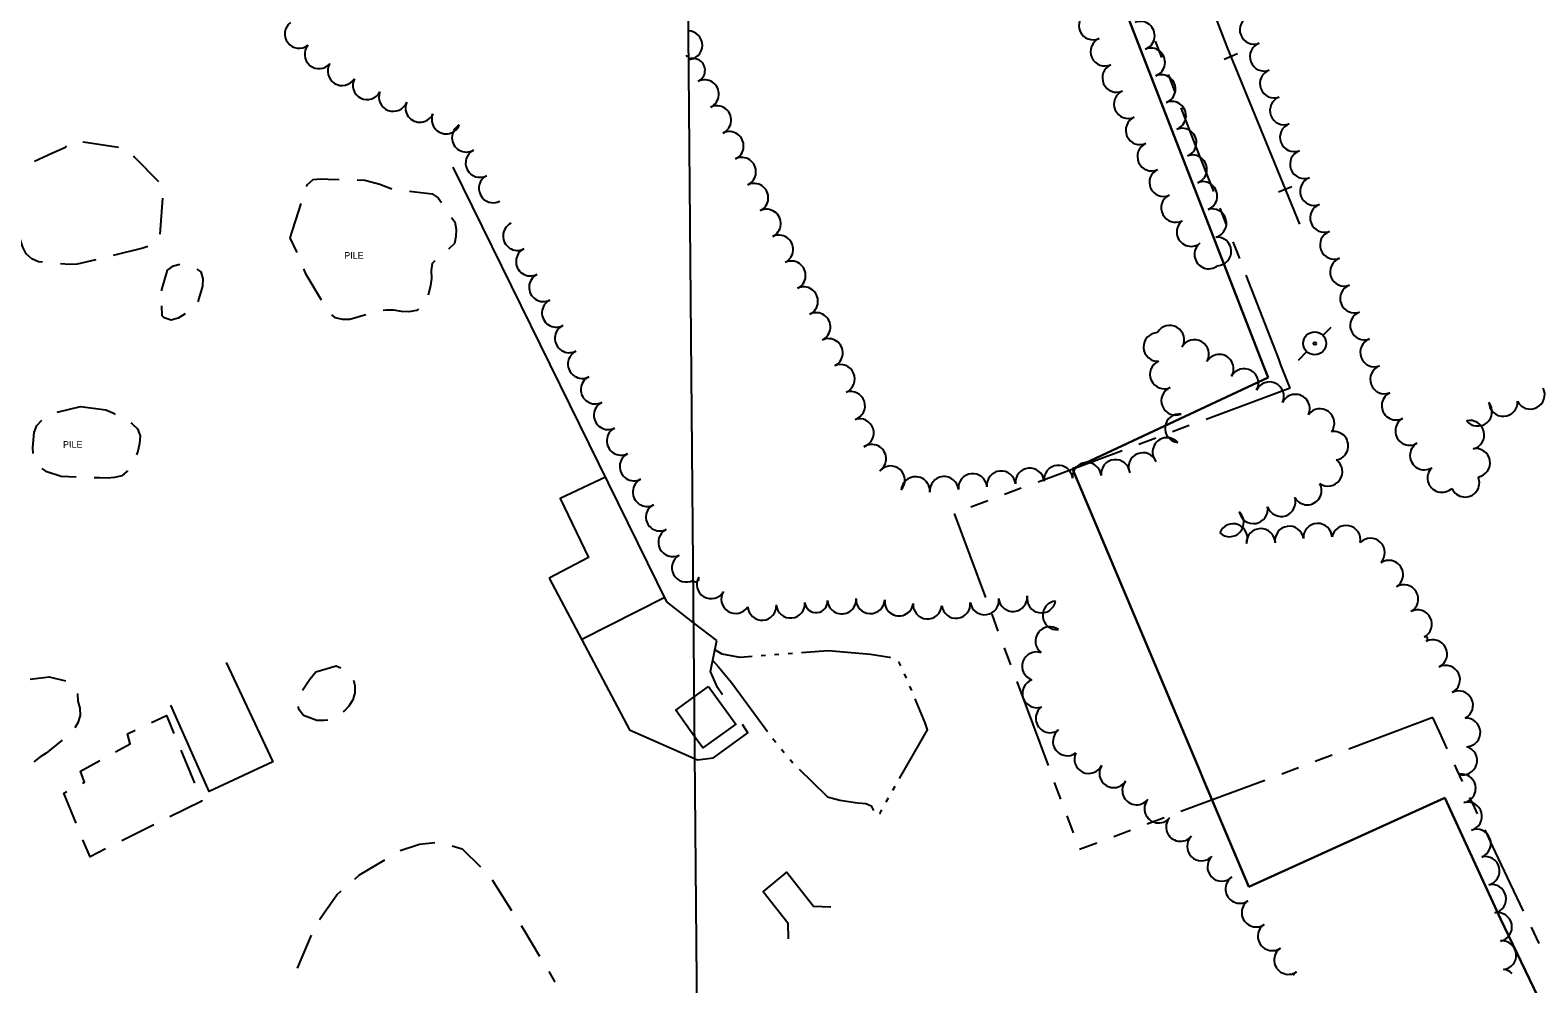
# Model space of a CAD drawing. Extents: x -2233 to 187241, y 4582 to 150524.
# Drawn here: x 104550 to 105601, y 57300 to 57965 of the extents above; entities that cross this region are included whole.
import ezdxf

# ---------------------------------------------------------------- set-up
doc = ezdxf.new("R2010")
doc.units = 0
for name, color, linetype in [('BLDG', 7, 'Continuous'), ('DIVISIONS', 7, 'Continuous'), ('DRIVWY', 7, 'Continuous'), ('DV_X_Corp_Line', 7, 'Continuous'), ('GRID', 7, 'Continuous'), ('ROAD', 7, 'Continuous'), ('RR', 7, 'Continuous'), ('TI_BORDER', 7, 'Continuous'), ('TRANSPWRLN', 7, 'Continuous'), ('TREES', 7, 'Continuous'), ('WALL', 7, 'Continuous'), ('WATER', 7, 'Continuous')]:
    doc.layers.add(name, color=color, linetype=linetype)

msp = doc.modelspace()

# ---------------------------------------------------------------- linework, layer by layer
at = {"layer": 'BLDG'}
for p, q in [((104642.7, 57847.4), (104640.8, 57822.5)), ((104731.6, 57819.9), (104739.3, 57843.7)), ((104736.5, 57809.7), (104731.6, 57819.9)), ((104569.3, 57698.4), (104585.5, 57702.3)), ((104740.3, 57504.6), (104745.3, 57512.3)), ((105013.1, 57499.9), (105023.2, 57507.2)), ((104655.4, 57462.9), (104665, 57439.8)), ((104669.8, 57428.3), (104670.1, 57427.4)), ((104670.1, 57427.4), (104647.8, 57416.3)), ((104636.6, 57410.7), (104614.2, 57399.6)), ((104872.5, 57372.4), (104885.9, 57351.2))]:
    msp.add_line(p, q, dxfattribs=at)
for points in [[(104553.4, 57873.2), (104565.6, 57878.9), (104575, 57883), (104575.9, 57883.8)], [(104587.2, 57886.8), (104589, 57886.5), (104611.9, 57883.1)], [(104622.4, 57876.9), (104623.2, 57876.1), (104639.9, 57859.1)], [(104743.1, 57855.6), (104743.6, 57857), (104747.6, 57860.4), (104752.8, 57861), (104758.1, 57860.8), (104765.8, 57860.6)], [(104778.3, 57860.2), (104783.7, 57860), (104794, 57857.2), (104802.4, 57854.1)], [(104814.7, 57852.4), (104830.5, 57850.5), (104834.7, 57847.7), (104837, 57844.4)], [(104844.1, 57834.1), (104846.4, 57830.9), (104847.4, 57825.9), (104847.1, 57820.7), (104846.2, 57815.8), (104842.5, 57812.3), (104842, 57811.9)], [(104559.1, 57802.9), (104556.2, 57803.2), (104551.5, 57805.1), (104547.5, 57808.7), (104545.3, 57813.3), (104543.7, 57818.2), (104542.9, 57819.2)], [(104632.5, 57813.8), (104629, 57812.7), (104608.3, 57807.6)], [(104596.2, 57804.6), (104583.2, 57801.4), (104577.9, 57801.2), (104571.6, 57801.8)], [(104641.9, 57782.8), (104646.1, 57797.4), (104650.2, 57800.4), (104654.8, 57801.6)], [(104666.6, 57797.9), (104669.4, 57796.2), (104670.8, 57791.3), (104670.6, 57786.1), (104667.2, 57775.2)], [(104753.5, 57776.4), (104742.8, 57794.2), (104741.2, 57798.2)], [(104832.5, 57803.8), (104830.5, 57802), (104829.9, 57797), (104830.2, 57791.6), (104829.5, 57786.6), (104827.7, 57780)], [(104658.5, 57766.9), (104653.5, 57763.8), (104648.6, 57762.4), (104643.8, 57764), (104642.4, 57765.5), (104642.2, 57772.4)], [(104784.3, 57766.1), (104773.3, 57762.9), (104768.1, 57762.9), (104763.3, 57764.2), (104760.7, 57766.3)], [(104821, 57770.1), (104819.6, 57769.2), (104814.3, 57768.2), (104809.1, 57768.4), (104803.9, 57769.4), (104798.6, 57769.4), (104796.4, 57769.1)], [(104585.5, 57702.3), (104603.2, 57699.9), (104607.9, 57697.9), (104609.6, 57696.8)], [(104552.6, 57669.5), (104552.3, 57673.7), (104553.2, 57684.3), (104555.1, 57689.1), (104558.6, 57692.7)], [(104620.6, 57690.9), (104621.6, 57690.3), (104625.2, 57686.7), (104627.1, 57681.8), (104626.6, 57676.6), (104625.4, 57671.2), (104624.4, 57668.6)], [(104582.4, 57653.1), (104572, 57653.5), (104561.9, 57656.7), (104558.7, 57659)], [(104618.2, 57657.8), (104618, 57657.3), (104614.2, 57654), (104609.2, 57652.9), (104604.2, 57652.4), (104598.8, 57652.5), (104594.9, 57652.7)], [(104550.5, 57512.2), (104563.6, 57514), (104575, 57511.1)], [(104745.3, 57512.3), (104749.5, 57517.4), (104763.6, 57521.6), (104767, 57520.2)], [(104583.2, 57502.4), (104583.3, 57502.1), (104583.7, 57497), (104585, 57492.1), (104585.2, 57487), (104583.6, 57481.9), (104581.6, 57478.4)], [(104775.7, 57511.7), (104776.7, 57507.8), (104776.8, 57502.8), (104775.3, 57497.9), (104772.5, 57493.5), (104769, 57489.8), (104768.6, 57489.5)], [(105023.2, 57507.2), (105042.2, 57481), (105019.3, 57464.5), (105013.3, 57472.7)], [(104757.8, 57483.7), (104755.4, 57483.4), (104750.3, 57483.5), (104740.9, 57486.9), (104737.9, 57490.9), (104737.3, 57493.3)], [(105013.3, 57472.7), (105000.3, 57490.7), (105013.1, 57499.9)], [(104635, 57482.1), (104645.5, 57486.9), (104650.6, 57474.5)], [(104609.9, 57461.7), (104620.1, 57467.3), (104618.2, 57474.3), (104623.6, 57476.8)], [(104572.8, 57469.7), (104561.5, 57460.7), (104557.1, 57458), (104552.9, 57454.6)], [(104586.9, 57439.9), (104588.2, 57440.6), (104585.5, 57448.3), (104598.9, 57455.7)], [(104582.4, 57411.9), (104573.8, 57432.8), (104575.9, 57434)], [(104603, 57394), (104592.1, 57388.6), (104587.2, 57400.4)], [(104808.3, 57392.9), (104821.7, 57397.4), (104832.5, 57398.5)], [(104776.6, 57373), (104780, 57376), (104797.5, 57386.5)], [(104844.6, 57396.1), (104851.4, 57394.1), (104864.3, 57381.6)], [(104752.1, 57344.9), (104764.2, 57362.1), (104767.2, 57364.8)], [(104736.8, 57310.8), (104736.8, 57310.8), (104746.4, 57333.9)], [(104892.5, 57340.7), (104894.5, 57337.6), (104905.4, 57319.2)], [(104911.8, 57308.5), (104915.9, 57301.7), (104916.1, 57301.4)]]:
    msp.add_lwpolyline(points, dxfattribs=at)
at = {"layer": 'DIVISIONS'}
for p, q in [((105339.2, 57945.4), (105334.7, 57957)), ((105348.2, 57922.1), (105343.7, 57933.7)), ((105384.3, 57828.8), (105379.8, 57840.5)), ((105420.6, 57735.6), (105397.9, 57793.8)), ((105428.6, 57715.2), (105370, 57693.3)), ((105358.3, 57689), (105346.6, 57684.6)), ((105311.5, 57671.5), (105252.9, 57649.7)), ((105334.9, 57680.3), (105323.2, 57675.9)), ((105241.2, 57645.3), (105229.5, 57640.9)), ((105217.8, 57636.6), (105206.1, 57632.2)), ((105194.4, 57627.8), (105216.2, 57569.3)), ((105220.6, 57557.6), (105224.9, 57545.8)), ((105229.3, 57534.1), (105233.7, 57522.4)), ((105238, 57510.7), (105259.9, 57452.1)), ((105528.1, 57485.5), (105469.5, 57463.6)), ((105434.4, 57450.5), (105422.7, 57446.2)), ((105457.8, 57459.3), (105446.1, 57454.9)), ((105264.2, 57440.4), (105268.6, 57428.7)), ((105411, 57441.8), (105352.4, 57420)), ((105273, 57417), (105277.4, 57405.3)), ((105340.7, 57415.6), (105329, 57411.2)), ((105293.8, 57398.1), (105281.7, 57393.6)), ((105317.3, 57406.9), (105305.6, 57402.5)), ((105602.1, 57328.2), (105596.7, 57339.4))]:
    msp.add_line(p, q, dxfattribs=at)
for points in [[(105375.3, 57852.1), (105362.7, 57884.5), (105352.7, 57910.4)], [(105393.4, 57805.5), (105391.6, 57810), (105388.9, 57817.1)], [(105428.6, 57715.2), (105422.2, 57731.4), (105420.6, 57735.6)], [(105538.1, 57463.8), (105532.7, 57475.5), (105528.1, 57485.5)], [(105548.6, 57441.1), (105545, 57449), (105543.4, 57452.5)], [(105559.2, 57418.5), (105557.3, 57422.6), (105553.9, 57429.8)], [(105591.3, 57350.7), (105582.2, 57369.7), (105569.7, 57396.1), (105564.5, 57407.2)]]:
    msp.add_lwpolyline(points, dxfattribs=at)
at = {"layer": 'DRIVWY'}
for points in [[(105032.9, 57501.4), (105029.5, 57506.5), (105024.5, 57517.7), (105028.9, 57539.3)], [(105013.5, 57457), (105015.5, 57456.1), (105026.7, 57457.6), (105050.7, 57475), (105046.9, 57480.7)]]:
    msp.add_lwpolyline(points, dxfattribs=at)
at = {"layer": 'DV_X_Corp_Line'}
for p, q in [((105409.5, 57731.9), (105253.6, 58133.5)), ((105409.5, 57731.9), (105253.6, 58133.5)), ((105253.6, 58133.5), (105409.5, 57731.9)), ((105253.6, 58133.5), (105409.5, 57731.9)), ((105286.1, 57663.1), (105413.2, 57722.5)), ((105286.1, 57663.1), (105413.2, 57722.5)), ((105413.2, 57722.5), (105286.1, 57663.1)), ((105413.2, 57722.5), (105286.1, 57663.1)), ((105413.2, 57722.5), (105409.5, 57731.9)), ((105413.2, 57722.5), (105409.5, 57731.9)), ((105409.5, 57731.9), (105413.2, 57722.5)), ((105409.5, 57731.9), (105413.2, 57722.5)), ((105277, 57658.8), (105286.1, 57663.1)), ((105277, 57658.8), (105286.1, 57663.1)), ((105286.1, 57663.1), (105277, 57658.8)), ((105286.1, 57663.1), (105277, 57658.8)), ((105365.8, 57448), (105277, 57658.8)), ((105365.8, 57448), (105277, 57658.8)), ((105277, 57658.8), (105365.8, 57448)), ((105277, 57658.8), (105365.8, 57448)), ((105367.7, 57443.4), (105365.8, 57448)), ((105367.7, 57443.4), (105365.8, 57448)), ((105365.8, 57448), (105367.7, 57443.4)), ((105365.8, 57448), (105367.7, 57443.4)), ((105399.7, 57367.7), (105367.7, 57443.4)), ((105399.7, 57367.7), (105367.7, 57443.4)), ((105367.7, 57443.4), (105399.7, 57367.7)), ((105367.7, 57443.4), (105399.7, 57367.7)), ((105536.3, 57429.6), (105399.7, 57367.7)), ((105536.3, 57429.6), (105399.7, 57367.7)), ((105399.7, 57367.7), (105536.3, 57429.6)), ((105399.7, 57367.7), (105536.3, 57429.6)), ((105575.3, 57345.2), (105536.3, 57429.6)), ((105575.3, 57345.2), (105536.3, 57429.6)), ((105536.3, 57429.6), (105575.3, 57345.2)), ((105536.3, 57429.6), (105575.3, 57345.2)), ((105601.2, 57291.2), (105575.3, 57345.2)), ((105601.2, 57291.2), (105575.3, 57345.2)), ((105575.3, 57345.2), (105601.2, 57291.2)), ((105575.3, 57345.2), (105601.2, 57291.2))]:
    msp.add_line(p, q, dxfattribs=at)
at = {"layer": 'GRID'}
msp.add_line((104991.3, 60000), (105014.8, 57302.3), dxfattribs=at)
at = {"layer": 'ROAD'}
msp.add_lwpolyline([(104912.1, 57582.7), (104968.1, 57476.9), (105013.5, 57457)], dxfattribs=at)
at = {"layer": 'RR'}
for p, q in [((105382.6, 57944.4), (105391.8, 57948.2)), ((105420.5, 57851.9), (105429.7, 57855.7))]:
    msp.add_line(p, q, dxfattribs=at)
msp.add_lwpolyline([(105007.1, 58925.1), (105096.6, 58702), (105289.2, 58201.1), (105384.5, 57953), (105435.1, 57829.4)], dxfattribs=at)
at = {"layer": 'TI_BORDER'}
msp.add_line((104999.5, 59062.3), (105026.2, 56000.1), dxfattribs=at)
at = {"layer": 'TRANSPWRLN'}
for p, q in [((105451.3, 57751.9), (105457.1, 57757.7)), ((105434.5, 57734.7), (105440.2, 57740.6))]:
    msp.add_line(p, q, dxfattribs=at)
for centre, radius in [((105445.7, 57746.3), 8.01), ((105445.7, 57746.2), 1)]:
    msp.add_circle(centre, radius, dxfattribs=at)
at = {"layer": 'TREES'}
for centre, radius, start, end in [((105291.3, 57967.8), 10, 114.0698, 294.0698), ((104737.9, 57962), 10, 127.6327, 307.6327), ((105324.2, 57960.7), 10, 291.3511, 111.3511), ((105403.5, 57964.8), 10, 110.472, 290.472), ((104751.7, 57947.7), 10, 139.9772, 319.9772), ((105008.9, 57954.1), 10, 269.351, 89.351), ((105299.5, 57949.6), 10, 114.0698, 294.0698), ((105410.5, 57946.1), 10, 110.472, 290.472), ((105008.3, 57947.6), 1.05, 211.6241, 329.3759), ((105012.4, 57936.5), 8.36, 295.6137, 115.6137), ((105331.4, 57942.1), 10, 291.3511, 111.3511), ((104767.8, 57936), 10, 148.2406, 328.2406), ((105307.7, 57931.3), 10, 114.0698, 294.0698), ((105338.7, 57923.5), 10, 291.3511, 111.3511), ((105417.5, 57927.3), 10, 110.472, 290.472), ((104785.3, 57926.2), 10, 153.0486, 333.0486), ((105020.4, 57920), 10, 295.6137, 115.6137), ((105315.8, 57913), 10, 114.0698, 294.0698), ((104803.5, 57918), 10, 158.7954, 338.7954), ((104822, 57910.4), 10, 156.2337, 336.2337), ((105029, 57901.9), 10, 295.6137, 115.6137), ((105346, 57904.9), 10, 291.3511, 111.3511), ((105424.5, 57908.6), 10, 110.472, 290.472), ((104840.3, 57902.3), 10, 156.2285, 336.2285), ((105324, 57894.8), 10, 114.0698, 294.0698), ((104854.4, 57889.6), 10, 119.7366, 299.7366), ((105037.7, 57883.9), 10, 295.6137, 115.6137), ((105353.3, 57886.2), 10, 291.3511, 111.3511), ((105431.5, 57889.9), 10, 110.472, 290.472), ((104863.9, 57872), 10, 117.3328, 297.3328), ((105332.1, 57876.5), 10, 114.0698, 294.0698), ((105438.5, 57871.1), 10, 110.472, 290.472), ((105046.3, 57865.9), 10, 295.6137, 115.6137), ((105360.6, 57867.6), 10, 291.3511, 111.3511), ((104873.1, 57854.3), 10, 117.3328, 297.3328), ((105340.2, 57858.5), 9.74, 114.0698, 294.0698), ((105445.5, 57852.4), 10, 110.472, 290.472), ((105054.9, 57847.8), 10, 295.6137, 115.6137), ((105348.7, 57840.7), 10, 117.0774, 297.0774), ((105367.8, 57849), 10, 291.3511, 111.3511), ((105063.6, 57829.8), 10, 295.6137, 115.6137), ((105374.2, 57830), 10, 285.7615, 105.7615), ((105452.5, 57833.7), 10, 110.472, 290.472), ((104890, 57821.1), 10, 116.8627, 296.8627), ((104885.5, 57830), 0.0000000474, 116.8548, 296.8548), ((105359.5, 57823.9), 10, 128.2891, 308.2891), ((105072.2, 57811.8), 10, 295.6137, 115.6137), ((105377.5, 57810.4), 10, 273.4576, 93.4576), ((105459.4, 57814.9), 10, 110.472, 290.472), ((104899, 57803.3), 10, 116.8627, 296.8627), ((105371.9, 57808.3), 10, 128.5812, 308.5812), ((105080.9, 57793.7), 10, 295.6137, 115.6137), ((105466.4, 57796.2), 10, 110.472, 290.472), ((104908.1, 57785.4), 10, 116.8627, 296.8627), ((105089.5, 57775.7), 10, 295.6137, 115.6137), ((105473.4, 57777.5), 10, 110.472, 290.472), ((104917.1, 57767.6), 10, 116.8627, 296.8627), ((105098.2, 57757.7), 10, 295.6137, 115.6137), ((105480.4, 57758.7), 10, 110.472, 290.472), ((104926.1, 57749.8), 10, 116.8627, 296.8627), ((105344.7, 57748.8), 10, 329.8288, 149.8288), ((105106.8, 57739.6), 10, 295.6137, 115.6137), ((105336.4, 57743.8), 10, 92.4358, 272.4358), ((105361.9, 57738.8), 10, 329.8229, 149.8229), ((105487.4, 57740), 10, 110.472, 290.472), ((104935.2, 57731.9), 10, 116.8627, 296.8627), ((105340.9, 57724.7), 10, 114.0428, 294.0428), ((105379.2, 57728.6), 10, 329.0612, 149.0612), ((104944.2, 57714.1), 10, 116.8627, 296.8627), ((105115.2, 57721.5), 10, 293.7142, 113.7142), ((105396.5, 57718.6), 10, 330.9893, 150.9893), ((105494.4, 57721.2), 10, 110.472, 290.472), ((105122.3, 57702.8), 10, 287.9124, 107.9124), ((105348.8, 57706.3), 10, 112.2586, 292.2586), ((105414.2, 57709.4), 10, 334.2286, 154.2286), ((105596, 57710.5), 10, 206.8863, 26.8863), ((104953.3, 57696.2), 10, 116.8627, 296.8627), ((105432.3, 57700.8), 10, 334.9113, 154.9113), ((105502.4, 57702.9), 10, 116.4322, 296.4322), ((105559.3, 57698.7), 10, 219.1974, 39.1974), ((105577.1, 57705.5), 10, 182.8323, 2.8323), ((105128.4, 57683.8), 10, 287.9124, 107.9124), ((105351.4, 57687.1), 10, 83.2342, 263.2342), ((105449.4, 57690.7), 10, 323.783, 143.783), ((105511.9, 57685.3), 10, 120.3448, 300.3448), ((105553.9, 57682.6), 10, 283.3836, 103.3836), ((104962.3, 57678.4), 10, 116.8627, 296.8627), ((105342.7, 57670.6), 10, 41.1749, 221.1749), ((105459.1, 57674.9), 10, 279.4616, 99.4616), ((105137, 57665.9), 10, 303.7227, 123.7227), ((105326, 57660.1), 10, 22.9899, 202.9899), ((105522.1, 57668.2), 10, 121.369, 301.369), ((105557.9, 57663), 10, 279.9937, 99.9937), ((104971.3, 57660.5), 10, 116.8627, 296.8627), ((105150.1, 57650.9), 10, 318.1917, 138.1917), ((105247.1, 57649.4), 10, 5.6131, 185.6131), ((105267, 57651.3), 10, 5.6131, 185.6131), ((105286.9, 57653.3), 10, 5.6131, 185.6131), ((105306.8, 57655.3), 10, 5.6131, 185.6131), ((105455, 57656.9), 10, 234.6332, 54.6332), ((105534.3, 57652.5), 10, 134.2455, 314.2455), ((104980.4, 57642.7), 10, 116.8627, 296.8627), ((105167.5, 57643.4), 10, 355.0388, 175.0388), ((105187.4, 57643.5), 10, 5.6131, 185.6131), ((105207.3, 57645.5), 10, 5.6131, 185.6131), ((105227.2, 57647.4), 10, 5.6131, 185.6131), ((105550.5, 57649.2), 10, 203.2648, 23.2648), ((105422.3, 57635.7), 10, 198.7066, 18.7066), ((105440.5, 57643.8), 10, 209.3461, 29.3462), ((104989.2, 57625.2), 9.64, 116.8627, 296.8627), ((105386.3, 57621.6), 10, 226.96, 46.96), ((105403, 57630.7), 10, 190.3426, 10.3426), ((105388.8, 57610.6), 10, 338.2017, 158.2017), ((105428, 57608.9), 10, 8.4938, 188.4938), ((105447.8, 57610.8), 10, 2.4646, 182.4646), ((105467.6, 57609.4), 10, 349.0336, 169.0336), ((104998.2, 57607.7), 10, 117.1796, 297.1796), ((105408.1, 57607.2), 10, 1.6899, 181.6899), ((105484.6, 57600.5), 10, 315.6385, 135.6385), ((105007.6, 57590), 10, 118.8521, 298.8521), ((105497.3, 57585.1), 10, 303.3975, 123.3975), ((105014.3, 57582.4), 2.25, 208.9148, 28.9148), ((105025, 57578.4), 10, 149.865, 329.865), ((105507.8, 57568.1), 10, 300.105, 120.105), ((105042.1, 57568.1), 10, 147.7254, 327.7254), ((105080.4, 57564.9), 10, 184.9429, 4.9429), ((105098.2, 57566.5), 7.87, 184.9429, 4.9429), ((105116.1, 57567.8), 10, 183.541, 3.541), ((105136, 57568), 10, 178.0389, 358.0389), ((105156, 57566.4), 10, 172.5228, 352.5228), ((105175.8, 57564.3), 10, 175.6866, 355.6866), ((105195.7, 57564.7), 10, 186.3837, 6.3837), ((105215.6, 57567.2), 10, 188.0842, 8.0842), ((105235.4, 57569.5), 10, 185.0325, 5.0325), ((105255.2, 57568.5), 10, 169.4464, 349.4464), ((105266.1, 57556.8), 10, 95.6242, 275.6242), ((105060.5, 57563.4), 10, 183.7897, 3.7897), ((105517.4, 57550.6), 10, 297.3011, 117.3011), ((105261.1, 57538.8), 10, 53.2638, 233.2638), ((105522.7, 57540.2), 1.68, 296.826, 116.826), ((105528, 57529.8), 10, 296.826, 116.826), ((105251.8, 57521.3), 10, 71.1791, 251.1791), ((105537, 57511.9), 10, 296.826, 116.826), ((105252, 57502.4), 10, 109.9512, 289.9512), ((105546.1, 57494.1), 10, 296.826, 116.826), ((105261.3, 57485), 10, 126.2171, 306.2171), ((105551.2, 57475.2), 10, 273.3969, 93.3969), ((105273.2, 57468.9), 10, 126.6805, 306.6805), ((105288.2, 57456.6), 10, 154.4574, 334.4574), ((105548.9, 57455.6), 10, 253.6258, 73.6258), ((105305.6, 57446.7), 10, 146.3696, 326.3696), ((105321.6, 57434.8), 10, 140.1677, 320.1677), ((105547.9, 57436.2), 10, 280.0429, 100.0429), ((105336.9, 57422), 9.9, 140.1677, 320.1677), ((105552.3, 57416.7), 10, 285.4048, 105.4048), ((105352.1, 57409.3), 10, 140.1677, 320.1677), ((105558.5, 57397.7), 10, 291.0793, 111.0793), ((105366.8, 57395.7), 10, 134.5532, 314.5532), ((105380.9, 57381.5), 10, 134.4976, 314.4976), ((105564.6, 57378.7), 10, 284.2012, 104.2012), ((105393.5, 57366.1), 10, 124.4227, 304.4227), ((105569.1, 57359.2), 10, 281.8192, 101.8192), ((105404.8, 57349.6), 10, 124.4227, 304.4227), ((105573.2, 57339.6), 10, 281.801, 101.801), ((105416.1, 57333.1), 10, 124.4227, 304.4227), ((105427.4, 57316.6), 10, 124.4227, 304.4227), ((105576.2, 57319.9), 10, 275.9178, 95.9178), ((105438.7, 57300.1), 9.97, 124.4227, 144.5162), ((105576.4, 57300), 10, 46.6922, 85.1203)]:
    msp.add_arc(centre, radius, start, end, dxfattribs=at)
at = {"layer": 'WALL'}
for p, q in [((104992.7, 57569.1), (104934.4, 57539.7)), ((105028.9, 57539.3), (105012.6, 57551.8))]:
    msp.add_line(p, q, dxfattribs=at)
for points in [[(105012.6, 57551.8), (104994.1, 57566.2), (104845.2, 57869)], [(104951.4, 57653), (104919.7, 57638.1), (104939.5, 57597.1), (104912.1, 57582.7)], [(104686.9, 57524), (104719.6, 57454.7), (104675.1, 57434), (104648.4, 57494.2)], [(105108.4, 57353.4), (105096.3, 57354), (105077.6, 57377.8), (105061.2, 57364.3), (105078.4, 57342.4), (105078.6, 57331.4)]]:
    msp.add_lwpolyline(points, dxfattribs=at)
at = {"layer": 'WATER'}
for p, q in [((105063, 57528.8), (105059.9, 57528.6)), ((105072.3, 57529.5), (105069.2, 57529.3)), ((105081.7, 57530.2), (105078.6, 57530)), ((105161.1, 57513.1), (105159.9, 57516)), ((105164.8, 57504.5), (105163.6, 57507.4)), ((105074, 57463.6), (105076, 57461.2)), ((105080, 57456.4), (105082, 57454)), ((105147.1, 57426.8), (105148.6, 57429.5)), ((105151.6, 57435), (105153.2, 57437.7))]:
    msp.add_line(p, q, dxfattribs=at)
for points in [[(105026.1, 57525.3), (105030, 57521.2), (105039.3, 57509.9), (105064.3, 57475.9)], [(105053.6, 57528.1), (105045.3, 57527.5), (105032.7, 57529.8), (105027.6, 57532.8)], [(105150, 57527.1), (105149.3, 57527.5), (105136, 57529.5), (105106.5, 57532), (105087.9, 57530.7)], [(105157.2, 57521.6), (105156.1, 57523.9), (105155.5, 57524.1)], [(105156.3, 57443.1), (105175.8, 57477), (105174.3, 57481.9), (105167.2, 57498.7)], [(105068, 57470.9), (105068.6, 57470.2), (105070, 57468.5)], [(105086.4, 57449.6), (105095.3, 57440.9), (105106.1, 57430.3), (105114.8, 57427.9), (105127.1, 57426.1), (105132.9, 57425.6), (105136.6, 57424.1), (105138.1, 57420.8)], [(105142.4, 57418.8), (105142.8, 57418.9), (105144.1, 57421.3)]]:
    msp.add_lwpolyline(points, dxfattribs=at)

# ---------------------------------------------------------------- texts
at = {"layer": 'BLDG'}
for p in [(104769.3, 57805.2), (104573.3, 57673.5)]:
    msp.add_text('PILE', height=4.68, rotation=0.5, dxfattribs=at).set_placement(p)

doc.saveas('drawing.dxf')
